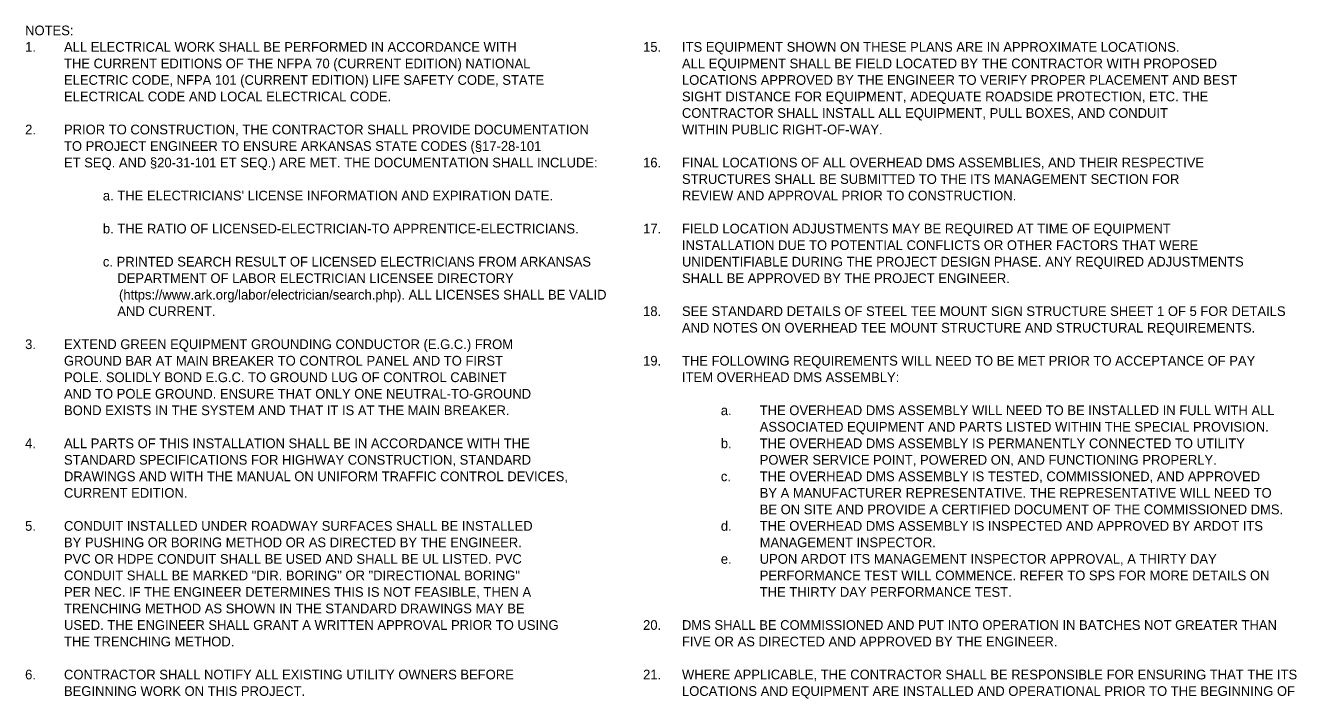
# Model space of a CAD drawing. Extents: x 118 to 1642, y 42 to 1033.
# Drawn here: x 118 to 1020, y 540 to 1018 of the extents above; entities that cross this region are included whole.
import ezdxf

# ---------------------------------------------------------------- set-up
doc = ezdxf.new("R2010")
doc.units = 0
doc.layers.add('C-ANNO-TEXT', color=7, linetype='Continuous')

msp = doc.modelspace()

# ---------------------------------------------------------------- texts
at = {"layer": 'C-ANNO-TEXT'}
for s, height, p in [('NOTES:', 6.899, (117.38, 1010.74)), ('1.', 6.899, (117.38, 999.01)), ('ALL ELECTRICAL WORK SHALL BE PERFORMED IN ACCORDANCE WITH ', 6.8991, (144.98, 999.01)), ('15.', 6.899, (556.11, 999.01)), ('ITS EQUIPMENT SHOWN ON THESE PLANS ARE IN APPROXIMATE LOCATIONS. ', 6.8991, (583.7, 999.01)), ('THE CURRENT EDITIONS OF THE NFPA 70 (CURRENT EDITION) NATIONAL ', 6.8991, (144.98, 987.28)), ('ALL EQUIPMENT SHALL BE FIELD LOCATED BY THE CONTRACTOR WITH PROPOSED ', 6.8991, (583.7, 987.28)), ('ELECTRIC CODE, NFPA 101 (CURRENT EDITION) LIFE SAFETY CODE, STATE ', 6.8991, (144.98, 975.55)), ('LOCATIONS APPROVED BY THE ENGINEER TO VERIFY PROPER PLACEMENT AND BEST ', 6.8991, (583.7, 975.55)), ('ELECTRICAL CODE AND LOCAL ELECTRICAL CODE. ', 6.8991, (144.98, 963.83)), ('SIGHT DISTANCE FOR EQUIPMENT, ADEQUATE ROADSIDE PROTECTION, ETC. THE ', 6.8991, (583.7, 963.83)), ('CONTRACTOR SHALL INSTALL ALL EQUIPMENT, PULL BOXES, AND CONDUIT ', 6.8991, (583.7, 952.1)), ('2.', 6.899, (117.38, 940.37)), ('PRIOR TO CONSTRUCTION, THE CONTRACTOR SHALL PROVIDE DOCUMENTATION ', 6.8991, (144.98, 940.37)), ('WITHIN PUBLIC RIGHT-OF-WAY.', 6.8991, (583.7, 940.37)), ('TO PROJECT ENGINEER TO ENSURE ARKANSAS STATE CODES (§17-28-101 ', 6.8991, (144.98, 928.64)), ('ET SEQ. AND §20-31-101 ET SEQ.) ARE MET. THE DOCUMENTATION SHALL INCLUDE:', 6.8991, (144.98, 916.91)), ('16.', 6.899, (556.11, 916.91)), ('FINAL LOCATIONS OF ALL OVERHEAD DMS ASSEMBLIES, AND THEIR RESPECTIVE ', 6.8991, (583.7, 916.91)), ('STRUCTURES SHALL BE SUBMITTED TO THE ITS MANAGEMENT SECTION FOR ', 6.8991, (583.7, 905.18)), ("a. THE ELECTRICIANS' LICENSE INFORMATION AND EXPIRATION DATE.", 6.8991, (172.58, 893.45)), ('REVIEW AND APPROVAL PRIOR TO CONSTRUCTION.', 6.8991, (583.7, 893.45)), ('b. THE RATIO OF LICENSED-ELECTRICIAN-TO APPRENTICE-ELECTRICIANS.', 6.8991, (172.58, 870)), ('17.', 6.899, (556.11, 870)), ('FIELD LOCATION ADJUSTMENTS MAY BE REQUIRED AT TIME OF EQUIPMENT ', 6.8991, (583.7, 870)), ('INSTALLATION DUE TO POTENTIAL CONFLICTS OR OTHER FACTORS THAT WERE ', 6.8991, (583.7, 858.27)), ('c. PRINTED SEARCH RESULT OF LICENSED ELECTRICIANS FROM ARKANSAS ', 6.8991, (172.58, 846.54)), ('UNIDENTIFIABLE DURING THE PROJECT DESIGN PHASE. ANY REQUIRED ADJUSTMENTS ', 6.8991, (583.7, 846.54)), ('    DEPARTMENT OF LABOR ELECTRICIAN LICENSEE DIRECTORY ', 6.8991, (172.58, 834.81)), ('SHALL BE APPROVED BY THE PROJECT ENGINEER.', 6.8991, (583.7, 834.81)), ('                          (https://www.ark.org/labor/electrician/search.php). ALL LICENSES SHALL BE VALID ', 6.89913, (117.38, 823.08)), ('    AND CURRENT.', 6.8991, (172.58, 811.36)), ('18.', 6.899, (556.11, 811.36)), ('SEE STANDARD DETAILS OF STEEL TEE MOUNT SIGN STRUCTURE SHEET 1 OF 5 FOR DETAILS ', 6.8991, (583.7, 811.36)), ('AND NOTES ON OVERHEAD TEE MOUNT STRUCTURE AND STRUCTURAL REQUIREMENTS.', 6.8991, (583.7, 799.63)), ('3.', 6.899, (117.38, 787.9)), ('EXTEND GREEN EQUIPMENT GROUNDING CONDUCTOR (E.G.C.) FROM ', 6.8991, (144.98, 787.9)), ('GROUND BAR AT MAIN BREAKER TO CONTROL PANEL AND TO FIRST ', 6.8991, (144.98, 776.17)), ('19.', 6.899, (556.11, 776.17)), ('THE FOLLOWING REQUIREMENTS WILL NEED TO BE MET PRIOR TO ACCEPTANCE OF PAY ', 6.8991, (583.7, 776.17)), ('POLE. SOLIDLY BOND E.G.C. TO GROUND LUG OF CONTROL CABINET ', 6.8991, (144.98, 764.44)), ('ITEM OVERHEAD DMS ASSEMBLY:', 6.8991, (583.7, 764.44)), ('AND TO POLE GROUND. ENSURE THAT ONLY ONE NEUTRAL-TO-GROUND ', 6.8991, (144.98, 752.71)), ('BOND EXISTS IN THE SYSTEM AND THAT IT IS AT THE MAIN BREAKER. ', 6.8991, (144.98, 740.98)), ('a.', 6.899, (611.3, 740.98)), ('THE OVERHEAD DMS ASSEMBLY WILL NEED TO BE INSTALLED IN FULL WITH ALL ', 6.8991, (638.9, 740.98)), ('ASSOCIATED EQUIPMENT AND PARTS LISTED WITHIN THE SPECIAL PROVISION.', 6.8991, (638.9, 729.26)), ('4.', 6.899, (117.38, 717.53)), ('ALL PARTS OF THIS INSTALLATION SHALL BE IN ACCORDANCE WITH THE ', 6.8991, (144.98, 717.53)), ('b.', 6.899, (611.3, 717.53)), ('THE OVERHEAD DMS ASSEMBLY IS PERMANENTLY CONNECTED TO UTILITY  ', 6.8991, (638.9, 717.53)), ('STANDARD SPECIFICATIONS FOR HIGHWAY CONSTRUCTION, STANDARD ', 6.8991, (144.98, 705.8)), ('POWER SERVICE POINT, POWERED ON, AND FUNCTIONING PROPERLY.', 6.8991, (638.9, 705.8)), ('DRAWINGS AND WITH THE MANUAL ON UNIFORM TRAFFIC CONTROL DEVICES, ', 6.8991, (144.98, 694.07)), ('c.', 6.899, (611.3, 694.07)), ('THE OVERHEAD DMS ASSEMBLY IS TESTED, COMMISSIONED, AND APPROVED ', 6.8991, (638.9, 694.07)), ('CURRENT EDITION.', 6.8991, (144.98, 682.34)), ('BY A MANUFACTURER REPRESENTATIVE. THE REPRESENTATIVE WILL NEED TO ', 6.8991, (638.9, 682.34)), ('BE ON SITE AND PROVIDE A CERTIFIED DOCUMENT OF THE COMMISSIONED DMS.', 6.8991, (638.9, 670.61)), ('5.', 6.899, (117.38, 658.88)), ('CONDUIT INSTALLED UNDER ROADWAY SURFACES SHALL BE INSTALLED ', 6.8991, (144.98, 658.88)), ('d.', 6.899, (611.3, 658.88)), ('THE OVERHEAD DMS ASSEMBLY IS INSPECTED AND APPROVED BY ARDOT ITS', 6.8991, (638.9, 658.88)), ('BY PUSHING OR BORING METHOD OR AS DIRECTED BY THE ENGINEER. ', 6.8991, (144.98, 647.16)), ('MANAGEMENT INSPECTOR.', 6.8991, (638.9, 647.16)), ('PVC OR HDPE CONDUIT SHALL BE USED AND SHALL BE UL LISTED. PVC ', 6.8991, (144.98, 635.43)), ('e.', 6.899, (611.3, 635.43)), ('UPON ARDOT ITS MANAGEMENT INSPECTOR APPROVAL, A THIRTY DAY ', 6.8991, (638.9, 635.43)), ('CONDUIT SHALL BE MARKED "DIR. BORING" OR "DIRECTIONAL BORING" ', 6.8991, (144.98, 623.7)), ('PERFORMANCE TEST WILL COMMENCE. REFER TO SPS FOR MORE DETAILS ON ', 6.8991, (638.9, 623.7)), ('PER NEC. IF THE ENGINEER DETERMINES THIS IS NOT FEASIBLE, THEN A ', 6.8991, (144.98, 611.97)), ('THE THIRTY DAY PERFORMANCE TEST.', 6.8991, (638.9, 611.97)), ('TRENCHING METHOD AS SHOWN IN THE STANDARD DRAWINGS MAY BE ', 6.8991, (144.98, 600.24)), ('USED. THE ENGINEER SHALL GRANT A WRITTEN APPROVAL PRIOR TO USING ', 6.8991, (144.98, 588.51)), ('20.', 6.899, (556.11, 588.51)), ('DMS SHALL BE COMMISSIONED AND PUT INTO OPERATION IN BATCHES NOT GREATER THAN ', 6.8991, (583.7, 588.51)), ('THE TRENCHING METHOD.', 6.8991, (144.98, 576.78)), ('FIVE OR AS DIRECTED AND APPROVED BY THE ENGINEER.', 6.8991, (583.7, 576.78)), ('6.', 6.899, (117.38, 553.33)), ('CONTRACTOR SHALL NOTIFY ALL EXISTING UTILITY OWNERS BEFORE ', 6.8991, (144.98, 553.33)), ('21.', 6.899, (556.11, 553.33)), ('WHERE APPLICABLE, THE CONTRACTOR SHALL BE RESPONSIBLE FOR ENSURING THAT THE ITS ', 6.8991, (583.7, 553.33)), ('BEGINNING WORK ON THIS PROJECT.', 6.8991, (144.98, 541.6)), ('LOCATIONS AND EQUIPMENT ARE INSTALLED AND OPERATIONAL PRIOR TO THE BEGINNING OF ', 6.8991, (583.7, 541.6))]:
    msp.add_text(s, height=height, rotation=0, dxfattribs=at).set_placement(p)

doc.saveas('drawing.dxf')
